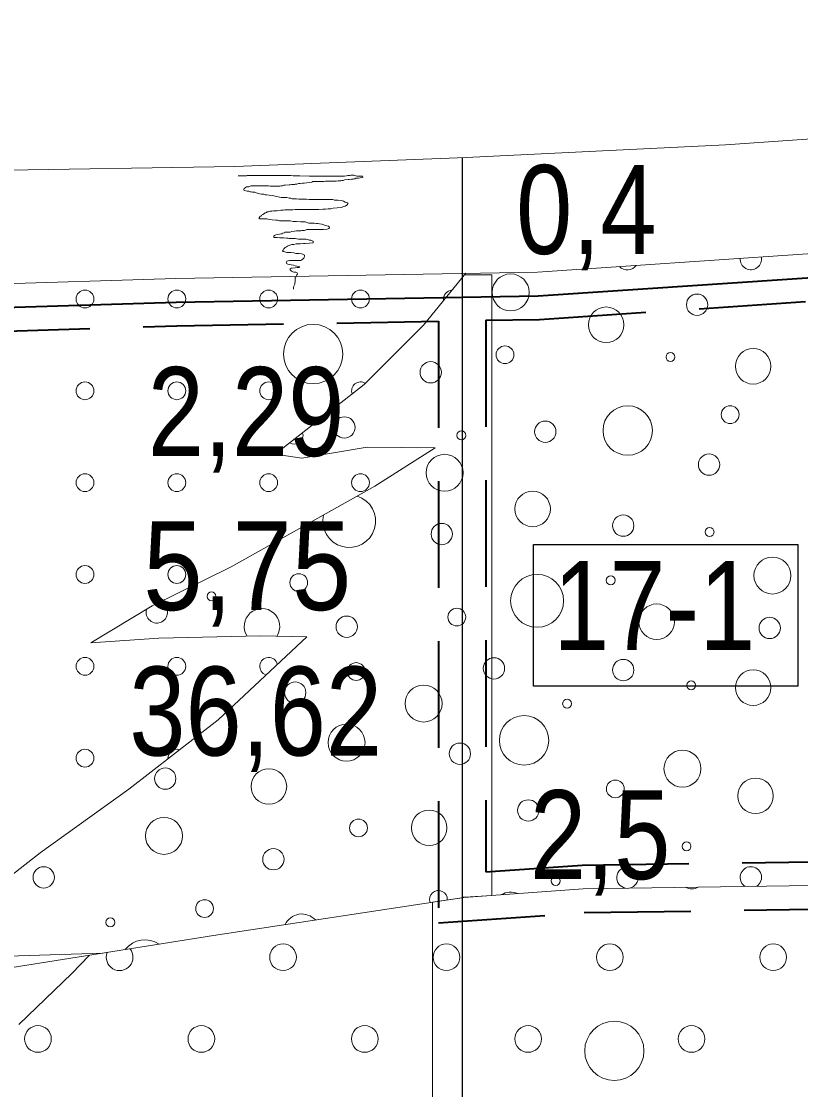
# Model space of a CAD drawing. Extents: x 640121 to 640955, y 6441885 to 6442246.
# Drawn here: x 640363.89 to 640390.2, y 6442176.5 to 6442212.56 of the extents above; entities that cross this region are included whole.
import ezdxf
from ezdxf.enums import TextEntityAlignment as Align

# ---------------------------------------------------------------- set-up
doc = ezdxf.new("R2010")
doc.units = 0
doc.header["$LTSCALE"] = 1.2
doc.linetypes.add('MEDIUM_DASHED', pattern=[4.5, 3, -1.5])
for name, color, linetype, lineweight in [('31', 7, 'Continuous', 13), ('32', 7, 'Continuous', 13), ('33', 7, 'Continuous', 13), ('35', 7, 'Continuous', 35), ('40', 7, 'Continuous', 13), ('41', 7, 'Continuous', 13), ('42', 7, 'Continuous', 13), ('43', 7, 'Continuous', 13), ('47', 7, 'Continuous', 13)]:
    doc.layers.add(name, color=color, linetype=linetype, lineweight=lineweight)

msp = doc.modelspace()

# ---------------------------------------------------------------- linework, layer by layer
at = {"layer": '31'}
for points in [[(640362.7, 6442207.53), (640371.1, 6442207.66), (640378.91, 6442207.96), (640387.66, 6442208.39), (640395.09, 6442208.91), (640403.04, 6442209.13), (640410.1, 6442209.62), (640417.94, 6442210.22), (640426.11, 6442210.87), (640434.35, 6442211.6), (640443.55, 6442211.39), (640450.84, 6442211.31), (640460.31, 6442211.42), (640471.64, 6442211.39), (640480.39, 6442211.46), (640490.9, 6442211.02), (640496.37, 6442211.02), (640502.28, 6442211.46), (640506.95, 6442212.04), (640510.5, 6442212.56)], [(640362.55, 6442203.68), (640369.1, 6442203.88), (640381.31, 6442204.1), (640393.24, 6442204.9), (640403.15, 6442205.61), (640412.11, 6442206.42), (640420.43, 6442207.78), (640428.21, 6442208.95), (640434.36, 6442209.59), (640443.5, 6442209.32), (640451.09, 6442208.86), (640456.15, 6442208.6), (640464.23, 6442208.39), (640474.43, 6442207.96), (640479.86, 6442207.51), (640485.77, 6442207.28), (640492.16, 6442206.96), (640495.99, 6442206.92), (640502.28, 6442207.34), (640510.5, 6442208.25)], [(640378.89, 6442204.06), (640377.47, 6442202.31), (640375.46, 6442200.3), (640372.46, 6442197.95), (640373.36, 6442197.82), (640375.56, 6442198.19), (640377.86, 6442198.17), (640375.82, 6442196.87), (640370.97, 6442194.15), (640368.3, 6442192.83), (640366.23, 6442191.58), (640368.53, 6442191.74), (640371.96, 6442191.82), (640373.53, 6442191.79), (640370.53, 6442188.99), (640367.52, 6442186.64), (640364.52, 6442184.5), (640359.94, 6442180.92), (640361.58, 6442180.92), (640363.79, 6442181.02), (640366.64, 6442181.11)], [(640361.87, 6442180.35), (640370.38, 6442181.71), (640378.83, 6442182.99), (640382.86, 6442183.28), (640390.58, 6442183.39), (640398.35, 6442183.34), (640407.42, 6442182.84), (640417.38, 6442182.24), (640426.85, 6442181.64), (640434.32, 6442181.74), (640441.06, 6442181.46), (640449.93, 6442181.22), (640459.93, 6442181.24), (640467.81, 6442181.49), (640476.37, 6442181.44), (640484.64, 6442181.24), (640496.4, 6442181.04), (640502.87, 6442181.04), (640510.5, 6442181.13)], [(640363.8, 6442178.7), (640365.59, 6442180.42), (640366.18, 6442181.03)]]:
    msp.add_lwpolyline(points, dxfattribs=at)
at = {"layer": '32', "lineweight": 25}
msp.add_line((640378.77, 6442207.95), (640378.77, 6442118.83), dxfattribs=at)
at = {"layer": '33'}
for points in [[(640379.77, 6442183.06), (640379.77, 6442204), (640378.89, 6442204), (640378.84, 6442204), (640378.77, 6442203.91), (640378.77, 6442183), (640378.83, 6442183), (640378.86, 6442183)], [(640377.77, 6442182.83), (640377.77, 6442158), (640378.77, 6442158), (640378.77, 6442182.98)]]:
    msp.add_lwpolyline(points, close=True, dxfattribs=at)
at = {"layer": '33', "lineweight": 25}
msp.add_lwpolyline([(640381.18, 6442194.9), (640390.1, 6442194.9), (640390.1, 6442190.12), (640381.18, 6442190.12)], close=True, dxfattribs=at)
at = {"layer": '35', "linetype": 'MEDIUM_DASHED'}
msp.add_line((640379.57, 6442202.47), (640379.57, 6442183.85), dxfattribs=at)
at = {"layer": '35', "lineweight": 40}
msp.add_lwpolyline([(640362.57, 6442202.88), (640369.12, 6442203.08), (640381.34, 6442203.3), (640393.27, 6442204.1)], dxfattribs=at)
at = {"layer": '35', "linetype": 'MEDIUM_DASHED'}
for points in [[(640379.57, 6442202.47), (640381.38, 6442202.5), (640393.32, 6442203.3)], [(640362.6, 6442202.08), (640369.14, 6442202.28), (640377.97, 6442202.44), (640377.97, 6442182.13)], [(640379.57, 6442183.85), (640382.82, 6442184.08), (640390.58, 6442184.19), (640398.38, 6442184.14), (640407.47, 6442183.64), (640417.43, 6442183.04), (640426.87, 6442182.44), (640434.33, 6442182.54), (640441.09, 6442182.26), (640449.94, 6442182.02), (640459.92, 6442182.04), (640467.8, 6442182.29), (640476.38, 6442182.24), (640484.66, 6442182.04), (640494.87, 6442181.87)], [(640377.97, 6442182.13), (640382.89, 6442182.48), (640390.58, 6442182.59), (640398.33, 6442182.54), (640407.37, 6442182.04), (640417.33, 6442181.44), (640426.83, 6442180.84), (640434.31, 6442180.94), (640441.03, 6442180.66), (640449.92, 6442180.42), (640459.94, 6442180.44), (640467.82, 6442180.69), (640476.36, 6442180.64), (640484.62, 6442180.44), (640494.87, 6442180.27)]]:
    msp.add_lwpolyline(points, dxfattribs=at)
at = {"layer": '40'}
for points in [[(640371.21, 6442207.35), (640371.27, 6442207.35), (640371.38, 6442207.35), (640371.49, 6442207.35), (640371.51, 6442207.36), (640371.62, 6442207.36), (640371.77, 6442207.36), (640372.1, 6442207.36), (640372.28, 6442207.36), (640372.31, 6442207.36), (640372.35, 6442207.36), (640372.42, 6442207.36), (640372.51, 6442207.36), (640372.61, 6442207.36), (640372.7, 6442207.36), (640372.76, 6442207.36), (640372.84, 6442207.36), (640372.91, 6442207.36), (640372.99, 6442207.36), (640373.07, 6442207.35), (640373.12, 6442207.35), (640373.19, 6442207.35), (640373.29, 6442207.35), (640373.62, 6442207.34), (640373.93, 6442207.33), (640374.03, 6442207.33), (640374.09, 6442207.33), (640374.13, 6442207.33), (640374.17, 6442207.33), (640374.25, 6442207.33), (640374.34, 6442207.34), (640374.39, 6442207.34), (640374.43, 6442207.34), (640374.45, 6442207.34), (640374.49, 6442207.34), (640374.56, 6442207.33), (640374.59, 6442207.33), (640374.64, 6442207.33), (640374.74, 6442207.34), (640374.8, 6442207.34), (640374.87, 6442207.35), (640374.91, 6442207.36), (640374.98, 6442207.36), (640375.01, 6442207.37), (640375.06, 6442207.37), (640375.11, 6442207.37), (640375.15, 6442207.36), (640375.18, 6442207.35), (640375.23, 6442207.34), (640375.27, 6442207.34)], [(640375.27, 6442207.34), (640375.31, 6442207.33), (640375.35, 6442207.33), (640375.4, 6442207.33), (640375.42, 6442207.3), (640375.4, 6442207.29), (640375.41, 6442207.3), (640375.37, 6442207.29), (640375.33, 6442207.28), (640375.27, 6442207.27), (640375.23, 6442207.27), (640375.18, 6442207.27), (640375.15, 6442207.25), (640375.11, 6442207.25), (640375.09, 6442207.23), (640375.03, 6442207.23), (640374.95, 6442207.22), (640374.92, 6442207.22), (640374.8, 6442207.21), (640374.75, 6442207.19), (640374.71, 6442207.19), (640374.67, 6442207.18), (640374.62, 6442207.18), (640374.58, 6442207.18), (640374.52, 6442207.17), (640374.49, 6442207.17), (640374.38, 6442207.17), (640374.32, 6442207.17), (640374.25, 6442207.17), (640374.16, 6442207.17), (640374.1, 6442207.16), (640374.05, 6442207.16), (640373.99, 6442207.15), (640373.93, 6442207.15), (640373.77, 6442207.15), (640373.73, 6442207.15), (640373.69, 6442207.13), (640373.62, 6442207.12), (640373.53, 6442207.11), (640373.44, 6442207.1), (640373.38, 6442207.1), (640373.3, 6442207.09), (640373.24, 6442207.09), (640373.19, 6442207.06), (640373.13, 6442207.06), (640373.11, 6442207.05), (640373.07, 6442207.05), (640373.01, 6442207.05), (640372.96, 6442207.04), (640372.93, 6442207.04), (640372.79, 6442207.03), (640372.75, 6442207.03)], [(640372.75, 6442207.03), (640372.71, 6442207.01), (640372.65, 6442207.01), (640372.61, 6442207), (640372.58, 6442207), (640372.54, 6442207), (640372.49, 6442207), (640372.45, 6442207), (640372.4, 6442207), (640372.33, 6442207), (640372.29, 6442207), (640372.23, 6442207.01), (640372.19, 6442207.01), (640372.16, 6442207.01), (640372.12, 6442207.01), (640372.07, 6442207.01), (640372.03, 6442207.01), (640371.95, 6442207.01), (640371.92, 6442207.01), (640371.88, 6442207.01), (640371.82, 6442207.01), (640371.79, 6442207.01), (640371.74, 6442207.01), (640371.7, 6442207.01), (640371.65, 6442207.01), (640371.61, 6442207), (640371.57, 6442206.98), (640371.52, 6442206.98), (640371.49, 6442206.97), (640371.46, 6442206.95), (640371.44, 6442206.94), (640371.41, 6442206.92), (640371.4, 6442206.88), (640371.41, 6442206.85), (640371.51, 6442206.83), (640371.57, 6442206.83), (640371.61, 6442206.81), (640371.65, 6442206.81), (640371.69, 6442206.8), (640371.71, 6442206.79), (640371.77, 6442206.79), (640371.82, 6442206.77), (640371.86, 6442206.76), (640371.93, 6442206.74), (640372, 6442206.73), (640372.07, 6442206.73), (640372.12, 6442206.71), (640372.17, 6442206.7), (640372.25, 6442206.69), (640372.36, 6442206.68)], [(640372.36, 6442206.68), (640372.51, 6442206.65), (640372.6, 6442206.63), (640372.66, 6442206.62), (640372.76, 6442206.61), (640372.85, 6442206.61), (640372.93, 6442206.59), (640372.99, 6442206.59), (640373.03, 6442206.57), (640373.12, 6442206.57), (640373.18, 6442206.57), (640373.26, 6442206.56), (640373.35, 6442206.56), (640373.42, 6442206.56), (640373.51, 6442206.56), (640373.6, 6442206.55), (640373.66, 6442206.55), (640373.69, 6442206.55), (640373.77, 6442206.55), (640373.84, 6442206.55), (640373.92, 6442206.55), (640374.02, 6442206.55), (640374.1, 6442206.55), (640374.16, 6442206.55), (640374.25, 6442206.55), (640374.28, 6442206.55), (640374.34, 6442206.55), (640374.4, 6442206.55), (640374.46, 6442206.53), (640374.52, 6442206.53), (640374.57, 6442206.52), (640374.7, 6442206.51), (640374.76, 6442206.49), (640374.82, 6442206.46), (640374.87, 6442206.45), (640374.91, 6442206.44), (640374.91, 6442206.4), (640374.89, 6442206.37), (640374.87, 6442206.35), (640374.85, 6442206.34), (640374.82, 6442206.32), (640374.77, 6442206.31), (640374.69, 6442206.28), (640374.55, 6442206.27), (640374.41, 6442206.25), (640374.34, 6442206.23), (640374.25, 6442206.23), (640374.16, 6442206.22), (640374.07, 6442206.22), (640373.93, 6442206.21), (640373.74, 6442206.21), (640373.57, 6442206.21)], [(640373.57, 6442206.21), (640373.49, 6442206.21), (640373.42, 6442206.21), (640373.33, 6442206.21), (640373.27, 6442206.21), (640373.21, 6442206.21), (640373.13, 6442206.21), (640373.05, 6442206.2), (640372.87, 6442206.2), (640372.78, 6442206.2), (640372.73, 6442206.19), (640372.65, 6442206.19), (640372.53, 6442206.16), (640372.4, 6442206.16), (640372.35, 6442206.15), (640372.29, 6442206.15), (640372.27, 6442206.14), (640372.23, 6442206.13), (640372.19, 6442206.13), (640372.16, 6442206.11), (640372.12, 6442206.1), (640372.1, 6442206.08), (640372.04, 6442206.04), (640372, 6442206.02), (640371.99, 6442205.99), (640371.95, 6442205.98), (640371.94, 6442205.96), (640371.92, 6442205.93), (640371.91, 6442205.91), (640371.93, 6442205.9), (640371.97, 6442205.9), (640372.03, 6442205.9), (640372.07, 6442205.9), (640372.18, 6442205.89), (640372.27, 6442205.87), (640372.36, 6442205.86), (640372.48, 6442205.85), (640372.54, 6442205.85), (640372.6, 6442205.83), (640372.66, 6442205.83), (640372.83, 6442205.83), (640372.96, 6442205.83), (640373.07, 6442205.81), (640373.18, 6442205.8), (640373.32, 6442205.79), (640373.47, 6442205.79), (640373.59, 6442205.75), (640373.67, 6442205.75), (640373.77, 6442205.75), (640373.85, 6442205.74)], [(640373.85, 6442205.74), (640373.9, 6442205.74), (640373.95, 6442205.73), (640374.03, 6442205.71), (640374.1, 6442205.69), (640374.15, 6442205.67), (640374.2, 6442205.66), (640374.26, 6442205.65), (640374.28, 6442205.63), (640374.29, 6442205.59), (640374.27, 6442205.57), (640374.25, 6442205.56), (640374.21, 6442205.55), (640374.09, 6442205.54), (640374.03, 6442205.54), (640373.99, 6442205.54), (640373.92, 6442205.54), (640373.84, 6442205.54), (640373.75, 6442205.53), (640373.71, 6442205.53), (640373.66, 6442205.53), (640373.53, 6442205.53), (640373.45, 6442205.5), (640373.42, 6442205.5), (640373.36, 6442205.5), (640373.32, 6442205.49), (640373.26, 6442205.49), (640373.18, 6442205.49), (640373.11, 6442205.48), (640373.02, 6442205.47), (640372.96, 6442205.45), (640372.93, 6442205.45), (640372.88, 6442205.45), (640372.84, 6442205.44), (640372.78, 6442205.44), (640372.77, 6442205.42), (640372.71, 6442205.41), (640372.69, 6442205.39), (640372.65, 6442205.39), (640372.6, 6442205.38), (640372.54, 6442205.37), (640372.48, 6442205.36), (640372.43, 6442205.33), (640372.41, 6442205.31), (640372.41, 6442205.26), (640372.45, 6442205.26), (640372.52, 6442205.26), (640372.61, 6442205.25), (640372.7, 6442205.25), (640372.75, 6442205.25), (640372.84, 6442205.24), (640372.9, 6442205.24)], [(640372.9, 6442205.24), (640372.93, 6442205.23), (640372.96, 6442205.23), (640373.02, 6442205.23), (640373.09, 6442205.23), (640373.13, 6442205.23), (640373.24, 6442205.21), (640373.32, 6442205.21), (640373.36, 6442205.21), (640373.41, 6442205.21), (640373.44, 6442205.21), (640373.5, 6442205.21), (640373.56, 6442205.2), (640373.61, 6442205.18), (640373.66, 6442205.17), (640373.71, 6442205.15), (640373.74, 6442205.14), (640373.74, 6442205.09), (640373.62, 6442205.07), (640373.47, 6442205.06), (640373.41, 6442205.06), (640373.3, 6442205.05), (640373.24, 6442205.05), (640373.17, 6442205.05), (640373.09, 6442205.03), (640373.02, 6442205.03), (640372.95, 6442205.01), (640372.87, 6442204.97), (640372.84, 6442204.95), (640372.79, 6442204.93), (640372.77, 6442204.9), (640372.75, 6442204.88), (640372.73, 6442204.84), (640372.71, 6442204.81), (640372.73, 6442204.79), (640372.78, 6442204.78), (640372.85, 6442204.76), (640372.99, 6442204.76), (640373.09, 6442204.75), (640373.15, 6442204.73), (640373.2, 6442204.72), (640373.27, 6442204.72), (640373.36, 6442204.71), (640373.45, 6442204.67), (640373.45, 6442204.63), (640373.44, 6442204.59), (640373.43, 6442204.57), (640373.36, 6442204.51), (640373.32, 6442204.49), (640373.26, 6442204.49), (640373.18, 6442204.49), (640373.09, 6442204.49), (640373.02, 6442204.49), (640372.94, 6442204.49), (640372.85, 6442204.47), (640372.84, 6442204.43), (640372.83, 6442204.41), (640372.84, 6442204.39), (640372.88, 6442204.37), (640373, 6442204.34), (640373.08, 6442204.33), (640373.13, 6442204.31), (640373.19, 6442204.3), (640373.25, 6442204.29), (640373.29, 6442204.27), (640373.26, 6442204.25), (640373.2, 6442204.25), (640373.13, 6442204.24), (640373.03, 6442204.23), (640373, 6442204.23), (640372.96, 6442204.22), (640372.96, 6442204.17), (640372.99, 6442204.15), (640373.01, 6442204.13), (640373.05, 6442204.11), (640373.09, 6442204.1), (640373.15, 6442204.09), (640373.2, 6442204.07), (640373.21, 6442204.03), (640373.19, 6442204), (640373.18, 6442203.97), (640373.15, 6442203.93), (640373.13, 6442203.91), (640373.13, 6442203.86), (640373.13, 6442203.81), (640373.13, 6442203.77), (640373.12, 6442203.74), (640373.12, 6442203.69), (640373.11, 6442203.67), (640373.09, 6442203.62), (640373.08, 6442203.58), (640373.08, 6442203.53), (640373.08, 6442203.52), (640373.08, 6442203.56)]]:
    msp.add_lwpolyline(points, dxfattribs=at)
at = {"layer": '41'}
for centre, radius in [((640380.407, 6442203.412), 0.624), ((640386.701, 6442202.995), 0.36), ((640383.632, 6442202.319), 0.6), ((640380.215, 6442201.308), 0.3), ((640388.594, 6442200.918), 0.6), ((640377.707, 6442200.716), 0.36), ((640385.801, 6442201.23), 0.15), ((640384.359, 6442198.749), 0.834), ((640387.817, 6442199.286), 0.3), ((640374.796, 6442198.853), 0.36), ((640381.576, 6442198.709), 0.36), ((640378.745, 6442198.587), 0.15), ((640378.176, 6442197.323), 0.624), ((640387.104, 6442197.601), 0.36), ((640381.148, 6442196.103), 0.6), ((640384.206, 6442195.542), 0.36), ((640378.082, 6442195.256), 0.36), ((640387.121, 6442195.326), 0.15), ((640389.243, 6442193.855), 0.624), ((640373.254, 6442193.616), 0.3), ((640381.299, 6442193.002), 0.893), ((640383.785, 6442193.694), 0.15), ((640370.308, 6442193.151), 0.15), ((640385.336, 6442192.296), 0.6), ((640374.874, 6442192.127), 0.36), ((640378.589, 6442192.452), 0.3), ((640389.151, 6442192.085), 0.36), ((640379.844, 6442190.72), 0.36), ((640384.206, 6442190.664), 0.36), ((640375.192, 6442190.615), 0.3), ((640388.594, 6442190.072), 0.6), ((640373.133, 6442189.903), 0.36), ((640386.5, 6442190.15), 0.15), ((640377.469, 6442189.534), 0.624), ((640382.312, 6442189.529), 0.15), ((640374.867, 6442188.214), 0.624), ((640380.86, 6442188.292), 0.835), ((640378.692, 6442187.839), 0.36), ((640386.206, 6442187.336), 0.624), ((640368.746, 6442187.001), 0.36), ((640372.246, 6442186.733), 0.6), ((640388.672, 6442186.421), 0.6), ((640383.941, 6442186.652), 0.3), ((640380.999, 6442185.925), 0.36), ((640377.656, 6442185.338), 0.6), ((640368.705, 6442185.068), 0.624), ((640375.27, 6442185.335), 0.3), ((640386.344, 6442184.714), 0.15), ((640372.397, 6442184.28), 0.36), ((640364.646, 6442183.668), 0.36), ((640381.925, 6442183.547), 0.15), ((640370.074, 6442182.614), 0.3), ((640366.894, 6442182.149), 0.15)]:
    msp.add_circle(centre, radius, dxfattribs=at)
for centre, radius, start, end in [((640384.348, 6442204.527), 0.36, 222.0335, 325.6393), ((640388.515, 6442204.537), 0.36, 176.4737, 11.1991), ((640373.098, 6442198.587), 0.3, 239.4544, 16.7251), ((640374.956, 6442195.691), 0.889, 166.2393, 72.3915), ((640368.463, 6442192.61), 0.36, 162.0205, 74.7015), ((640372.012, 6442192.14), 0.6, 326.7088, 213.4615), ((640384.348, 6442183.658), 0.36, 282.5652, 259.0675), ((640388.515, 6442183.668), 0.36, 303.4501, 238.1826), ((640377.968, 6442182.923), 0.3, 357.0017, 200.3446), ((640380.407, 6442182.543), 0.624, 68.4414, 119.8158), ((640373.356, 6442181.807), 0.624, 42.4704, 154.8759), ((640368.064, 6442180.721), 0.838, 55.3942, 142.7488)]:
    msp.add_arc(centre, radius, start, end, dxfattribs=at)
at = {"layer": '42'}
for centre in [(640372.723, 6442180.971), (640378.239, 6442180.971), (640383.754, 6442180.971), (640389.27, 6442180.971), (640364.45, 6442178.213), (640369.966, 6442178.213), (640375.481, 6442178.213), (640380.997, 6442178.213), (640386.512, 6442178.213)]:
    msp.add_circle(centre, 0.45, dxfattribs=at)
for centre, start, end in [((640386.512, 6442183.728), 241.4232, 300.2095), ((640367.208, 6442180.971), 159.1272, 39.0158)]:
    msp.add_arc(centre, 0.45, start, end, dxfattribs=at)
at = {"layer": '43'}
for centre in [(640366.038, 6442203.19), (640369.138, 6442203.19), (640372.238, 6442203.19), (640375.338, 6442203.19), (640366.038, 6442200.09), (640369.138, 6442200.09), (640372.238, 6442200.09), (640366.038, 6442196.99), (640369.138, 6442196.99), (640372.238, 6442196.99), (640375.338, 6442196.99), (640366.038, 6442193.89), (640369.138, 6442193.89), (640366.038, 6442190.79), (640369.138, 6442190.79), (640366.038, 6442187.69)]:
    msp.add_circle(centre, 0.3, dxfattribs=at)
for centre, start, end in [((640378.438, 6442203.19), 91.8189, 189.7667), ((640375.338, 6442200.09), 56.965, 200.661), ((640372.238, 6442190.79), 13.0789, 253.0074), ((640369.138, 6442187.69), 72.0715, 183.8716)]:
    msp.add_arc(centre, 0.3, start, end, dxfattribs=at)
at = {"layer": '47'}
for centre in [(640373.742, 6442201.332), (640383.906, 6442177.81)]:
    msp.add_circle(centre, 1, dxfattribs=at)

# ---------------------------------------------------------------- texts
at = {"layer": '32', "width": 0.85}
for s, p in [('0,4', (640382.96, 6442204.71)), ('2,29', (640371.475, 6442197.89)), ('36,62', (640371.8, 6442187.78)), ('2,5', (640383.43, 6442183.61))]:
    msp.add_text(s, height=3, dxfattribs=at).set_placement(p, align=Align.CENTER)
at = {"layer": '33'}
for s, width, p in [('5,75', 0.9, (640371.515, 6442192.69)), ('17-1', 0.85, (640385.255, 6442191.34))]:
    msp.add_text(s, height=3, dxfattribs=dict(at, width=width)).set_placement(p, align=Align.CENTER)

doc.saveas('drawing.dxf')
